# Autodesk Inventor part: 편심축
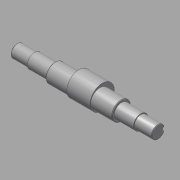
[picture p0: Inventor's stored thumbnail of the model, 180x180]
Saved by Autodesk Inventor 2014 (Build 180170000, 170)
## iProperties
Created: 2015-10
Part Number: 편심축
Document SubType Name: Modeling
Designer: mdu
Density: 7.86 g/cm^3
Material: 강철, 연강
Mass: 1327.93 g
Surface Area: 248.524 cm^2
Volume: 168.947 cm^3
Appearance: 강철
Author: mdu
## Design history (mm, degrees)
sketch "스케치1"
  geometry: L1 (-20.5, -41.331)-(-20.5, 32.669) reference; L2 (7.5, -30.031)-(7.5, 21.369) reference; L3 (135.5, -30.331)-(135.5, 21.669) reference; L4 (121.5, 21.369)-(121.5, -30.031) reference; L5 (184.5, -4.331)-(-57.5, -4.331); L6 (184.5, -4.331)-(184.5, 6.669); L7 (154.5, 8.169)-(121.5, 8.169); L8 (121.5, 8.169)-(121.5, 11.669); L9 (121.5, 11.669)-(7.5, 11.669); L10 (7.5, 11.669)-(7.5, 8.169); L11 (7.5, 8.169)-(-27.5, 8.169); L12 (-27.5, 8.169)-(-27.5, 6.669); L13 (-27.5, 6.669)-(-57.5, 6.669); L14 (-57.5, 6.669)-(-57.5, -4.331); L15 (154.5, 8.169)-(154.5, 6.669); L16 (154.5, 6.669)-(184.5, 6.669); C1 r 32.5 at (64.5, -4.331) reference; 1 further point
  constraints: 24 end point, 8 perpendicular, 5 point on line, 3 parallel, 2 collinear
  dimensions: "d1" = 25 diameter of L11 L5; "d2" = 32 diameter of L9 L5; "d3" = 22 diameter of L13 L5; "d4" = 35 distance of L10.end L11.end; "d5" = 30 distance of L12.end L13.end; "d15" = 33 distance of L7.start L7.end; "d26" = 30 distance of L15.end L6.end
revolve "회전1" sketch "스케치1" stored, may be unused: angle "d6" = 90 deg
node "작업 평면1"
sketch "스케치2"
  geometry: C1 r 16 at (0, 0) reference; C2 r 16 at (0, 0) reference; C3 r 20.75 at (0, 4); C4 r 16 at (0, 0) reference; 1 further point
  constraints: 1 centre point, 1 vertical alignment
  dimensions: "d8" = 41.5 diameter of C3; "d25" = 4 distance of C3.centre C1.centre
extrude "돌출1" join sketch "스케치2" stored distance "d9" = 40; taper "d10" = 0 deg
chamfer "모따기1" distance "d11" = 1; stored, may be unused: second distance "d12" = 2, angle "d13" = 45 deg
node "작업 평면2"
sketch "스케치3"
  geometry: L1 (-15, -10)-(-15, 10) reference; L2 (-15, 3)-(0, 3); L3 (0, -3)-(-15, -3); A1 r 3 centre (0, 0) between (0, -3) and (0, 3); 2 further points
  constraints: 4 end point, 2 perpendicular, 2 point on circle, 2 point on line, 2 tangent, 1 centre point, 1 horizontal alignment, 1 midpoint
  dimensions: "d16" = 18 dimension on A1 L1; "d17" = 6 distance between parallel lines of L3 L2
extrude "돌출2" cut sketch "스케치3" distance "d18" = 3.5; taper "d19" = 0 deg
node "작업 평면3"
node "솔리드1"
mirror "대칭1"
node "참조1"
node "참조2"
node "참조3"
node "참조4"
node "참조5"
node "투영된 루프1"
